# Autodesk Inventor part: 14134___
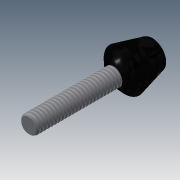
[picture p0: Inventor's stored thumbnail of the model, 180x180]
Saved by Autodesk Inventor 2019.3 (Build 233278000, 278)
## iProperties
Created: 2010-06
Part Number: 14134___
Material: Ogólny
Document SubType Name: Modeling
Designer: CADENGINEERING4
Density: 1 g/cm^3
Appearance: Domyślna
Author: CADENGINEERING4
Revision Number: ANY
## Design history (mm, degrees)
feature "NONE"
node "Bryła1"
